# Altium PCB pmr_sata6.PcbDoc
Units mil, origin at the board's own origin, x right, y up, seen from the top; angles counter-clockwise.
Board outline 6299.21 x 3934 mil, 2 copper layers (Top Layer, Bottom Layer); 11 components, 38 nets, 173 pads, 16 vias.
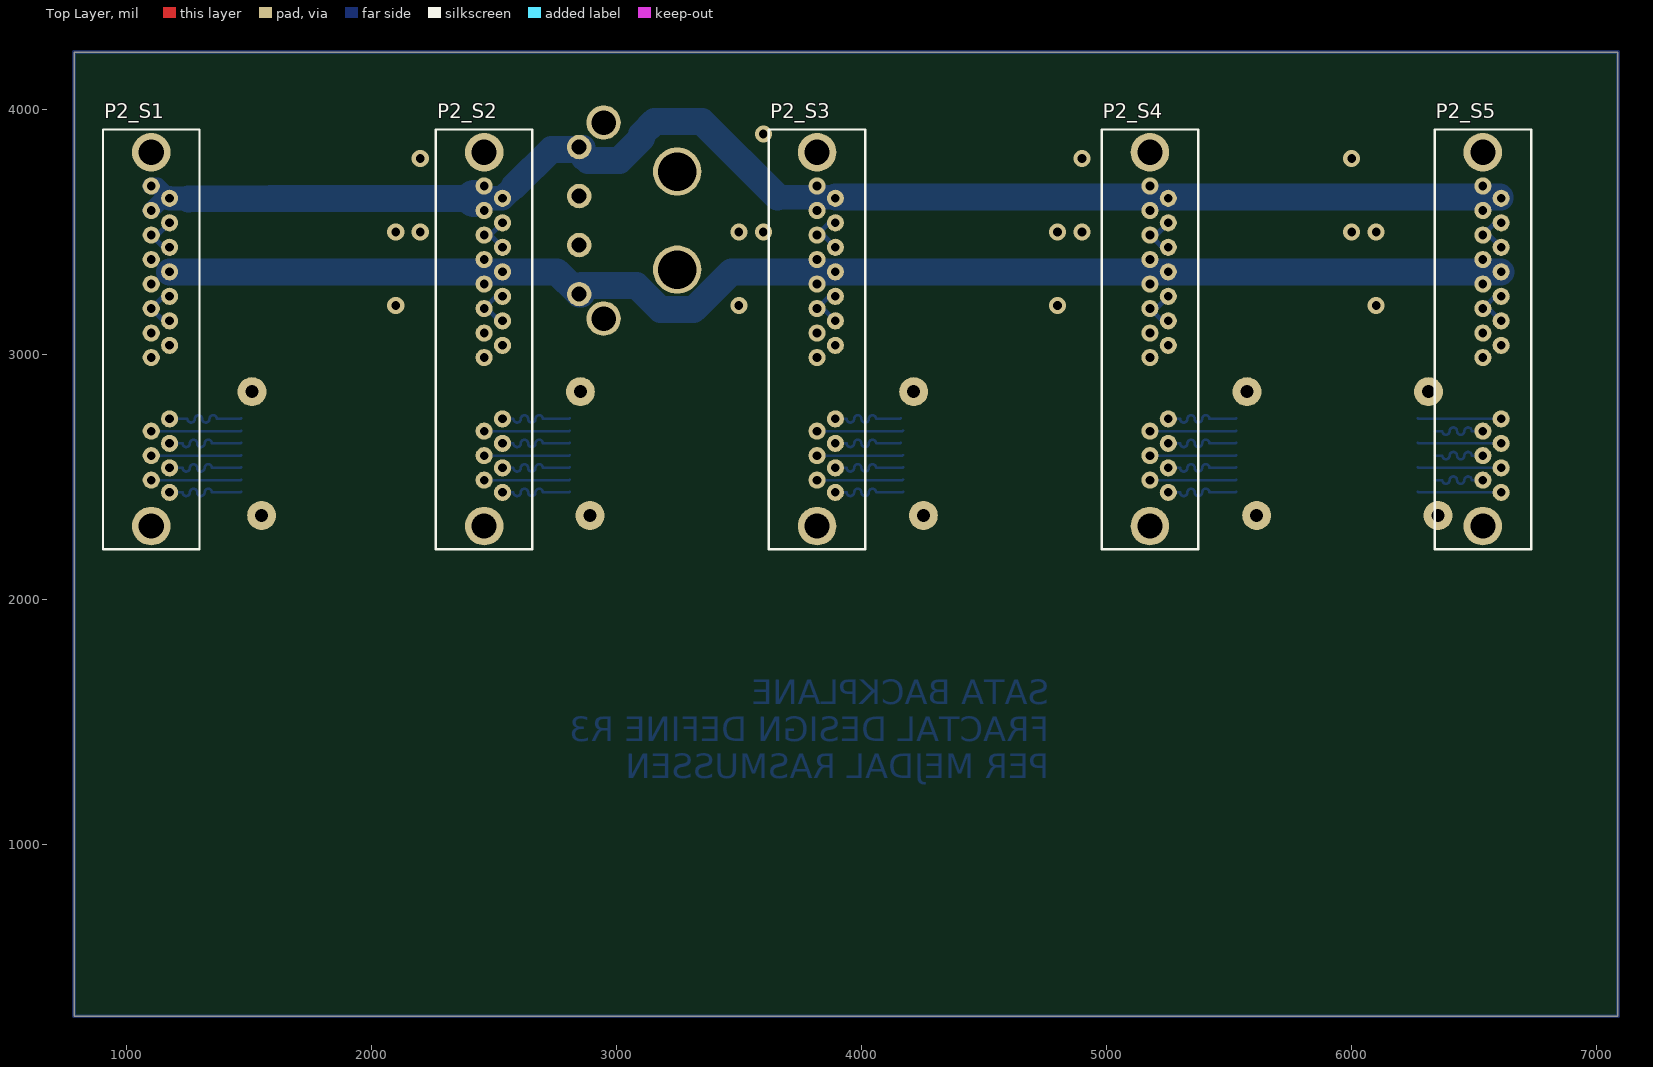
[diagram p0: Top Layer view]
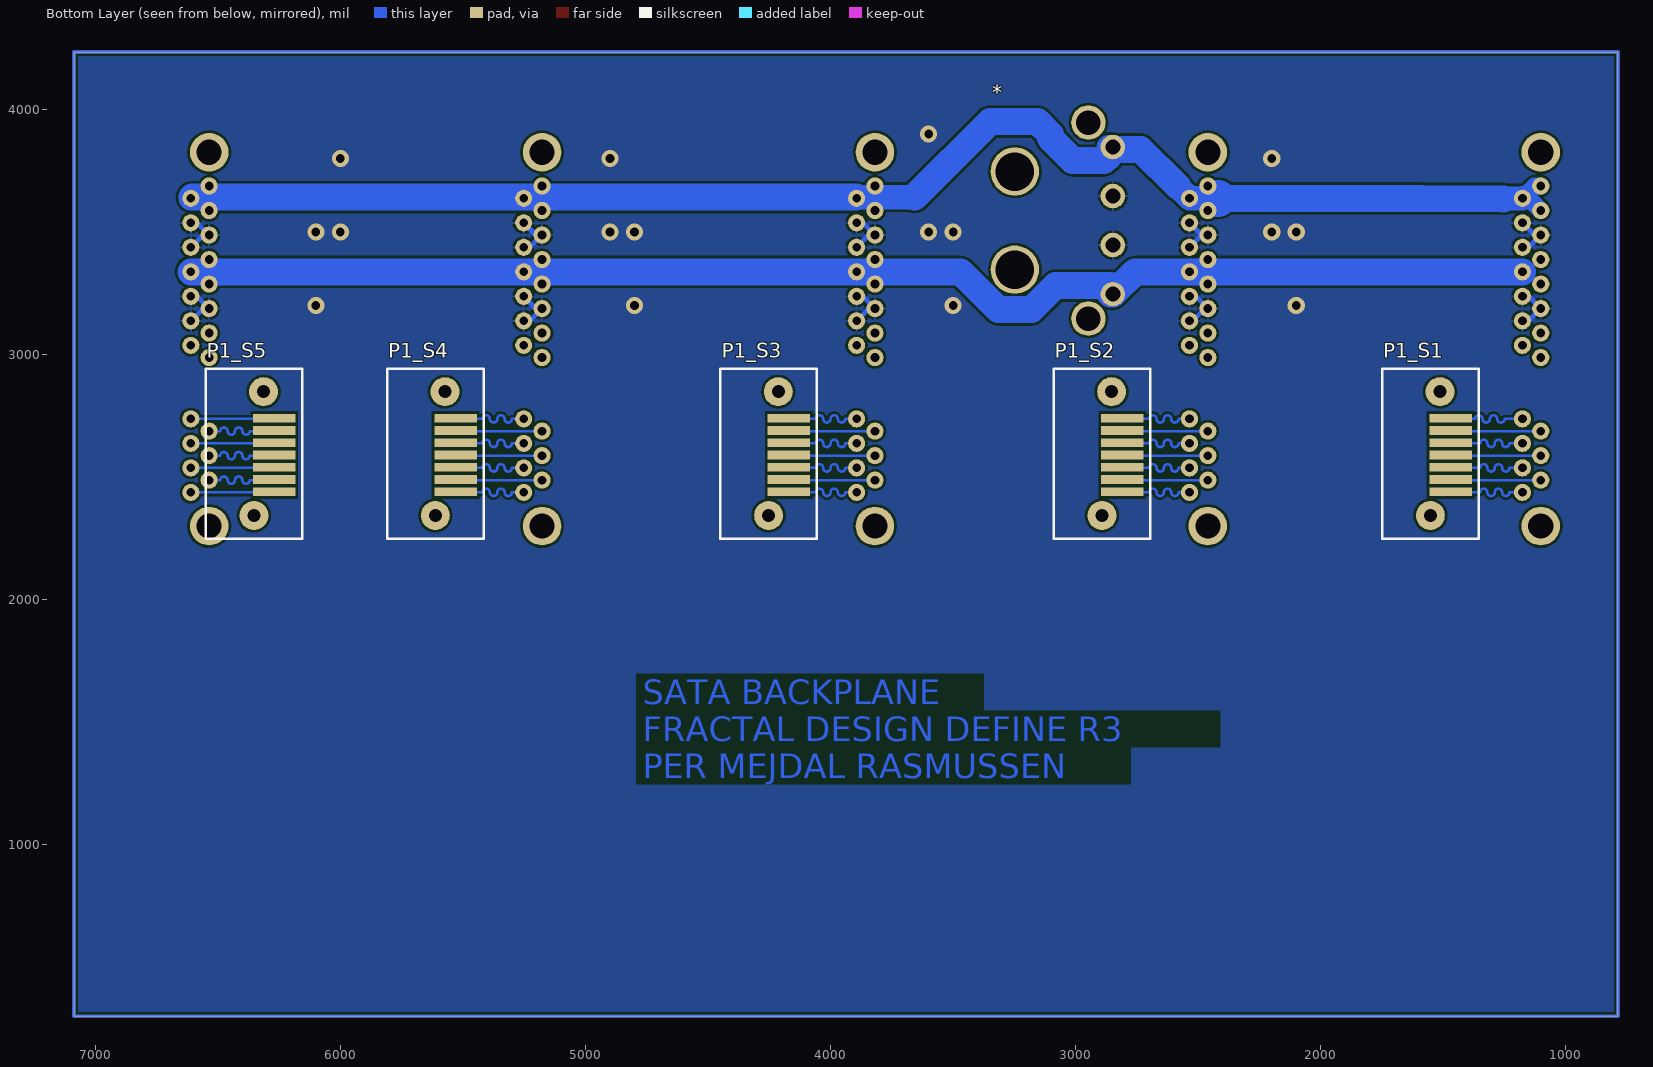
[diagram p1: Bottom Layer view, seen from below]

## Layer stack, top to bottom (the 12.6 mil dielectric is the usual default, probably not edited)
Top Solder: solder mask 0.4, Solder Resist, Dk 3.5
Top Layer: signal copper 1.4
Dielectric1: dielectric 12.6, FR-4, Dk 4.8
Bottom Layer: signal copper 1.4
Bottom Solder: solder mask 0.4, Solder Resist, Dk 3.5

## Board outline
787.4,300 787.4,4234 7086.61,4234 7086.61,300

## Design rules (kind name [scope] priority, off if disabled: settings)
Clearance [All] p1: gap=10
DiffPairsRouting [All] p1: maxlimit=10 minlimit=10 mostfreqgap=10 toplayer_minwidth=10 toplayer_maxwidth=15 toplayer_prefwidth=15 bottomlayer_minwidth=10 bottomlayer_maxwidth=15 bottomlayer_prefwidth=15 maxuncoupledlength=500
PolygonConnect [All] p1: connectstyle=Relief reliefconductorwidth=10 reliefentries=4 polygonreliefangle="90 Angle" airgapwidth=10
RoomDefinition top_level_sheet [InComponentClass('top_level_sheet')] p1 off: confinementstyle=ConfineIn formatcopy=TRUE lockcomponents=FALSE outline 7086.61,393.7 7775.59,393.7 7775.59,1476.38 7086.61,1476.38
RoomDefinition S5 [InComponentClass('S5')] p2 off: confinementstyle=ConfineIn formatcopy=TRUE lockcomponents=FALSE outline 1141.73,4803.15 2086.61,4803.15 2086.61,6692.91 1141.73,6692.91
RoomDefinition S3 [InComponentClass('S3')] p3 off: confinementstyle=ConfineIn formatcopy=TRUE lockcomponents=FALSE outline 2992.13,4520.87 3937.01,4520.87 3937.01,6410.63 2992.13,6410.63
RoomDefinition S2 [InComponentClass('S2')] p4 off: confinementstyle=ConfineIn formatcopy=TRUE lockcomponents=FALSE outline 4251.97,4527.56 5196.85,4527.56 5196.85,6417.32 4251.97,6417.32
RoomDefinition S1 [InComponentClass('S1')] p5 off: confinementstyle=ConfineIn formatcopy=TRUE lockcomponents=FALSE outline 5000,4566.93 5944.88,4566.93 5944.88,6456.69 5000,6456.69
RoomDefinition S4 [InComponentClass('S4')] p6 off: confinementstyle=ConfineIn formatcopy=TRUE lockcomponents=FALSE outline 7570,1160 7280,1160 7280,1590 7570,1590
RoutingVias [All] p1: holewidth=28 width=50 viastyle="Through Hole" minholewidth=28 minwidth=50 maxholewidth=28 maxwidth=50
SilkToSolderMaskClearance SilkscreenOverComponentPads [IsPad] p1: minsilkscreentomaskgap=10 clearancetoexposedcopper=TRUE
SolderMaskExpansion [All] p1: expansion=4
Width [All] p1: maxlimit=500 minlimit=10 preferedwidth=10
28 further rules are at their usual default settings.

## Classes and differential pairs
component class top_level_sheet: *
channel class pmr_sata_single: S1 S2 S3 S4 S5
component class S5: P1_S5 P2_S5
component class S4: P1_S4 P2_S4
component class S3: P1_S3 P2_S3
component class S2: P1_S2 P2_S2
component class S1: P1_S1 P2_S1
differential pair PAIR2_S5: +PAIR2_S5_P -PAIR2_S5_N
differential pair PAIR2_S4: +PAIR2_S4_P -PAIR2_S4_N
differential pair PAIR2_S3: +PAIR2_S3_P -PAIR2_S3_N
differential pair PAIR2_S2: +PAIR2_S2_P -PAIR2_S2_N
differential pair PAIR2_S1: +PAIR2_S1_P -PAIR2_S1_N
differential pair PAIR1_S5: +PAIR1_S5_P -PAIR1_S5_N
differential pair PAIR1_S4: +PAIR1_S4_P -PAIR1_S4_N
differential pair PAIR1_S3: +PAIR1_S3_P -PAIR1_S3_N
differential pair PAIR1_S2: +PAIR1_S2_P -PAIR1_S2_N
differential pair PAIR1_S1: +PAIR1_S1_P -PAIR1_S1_N

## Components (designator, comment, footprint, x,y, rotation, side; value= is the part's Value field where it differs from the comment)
* "PC_PWR_MOLEX" PC_PWR_MOLEX 3248.03,3546.46 r90 bottom
P1_S1 "SATA lille" "PMR_SATA -LILLE NY" 1552.68,2343.15 r270 bottom (schematic designator P1)
P1_S2 "SATA lille" "PMR_SATA -LILLE NY" 2892.68,2343.15 r270 bottom (schematic designator P1)
P1_S3 "SATA lille" "PMR_SATA -LILLE NY" 4252.68,2343.15 r270 bottom (schematic designator P1)
P1_S4 "SATA lille" "PMR_SATA -LILLE NY" 5612.68,2343.15 r270 bottom (schematic designator P1)
P1_S5 "SATA lille" "PMR_SATA -LILLE NY" 6352.68,2343.15 r270 bottom (schematic designator P1)
P2_S1 "SATA STOR" pmr_sata 1102.36,2300 r90 top (schematic designator P2)
P2_S2 "SATA STOR" pmr_sata 2460.63,2300 r90 top (schematic designator P2)
P2_S3 "SATA STOR" pmr_sata 3818.9,2300 r90 top (schematic designator P2)
P2_S4 "SATA STOR" pmr_sata 5177.17,2300 r90 top (schematic designator P2)
P2_S5 "SATA STOR" pmr_sata 6535.43,2300 r90 top (schematic designator P2)

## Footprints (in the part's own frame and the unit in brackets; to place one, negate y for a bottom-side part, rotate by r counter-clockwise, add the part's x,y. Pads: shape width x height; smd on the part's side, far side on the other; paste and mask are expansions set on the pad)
PC_PWR_MOLEX [mil]
  round 100 hole 60: 1(300,-400) 2(100,-400) 3(-100,-400) 4(-300,-400)
  round 140 hole 100: 5(400,-300) 6(-400,-300)
  round 196.85 hole 157.48: 7(-200,0) 8(200,0)
pmr_sata [mm]
  round 1.778 hole 0.9: P1(17.46,0) P2(18.73,-1.9) P3(20,0) P4(21.27,-1.9) P5(22.54,0) P6(23.81,-1.9) P7(25.08,0) P8(26.35,-1.9) P9(27.62,0) P10(28.89,-1.9) P11(30.16,0) P12(31.43,-1.9) P13(32.7,0) P14(33.97,-1.9) P15(35.24,0) S1(3.49,-1.9) S2(4.76,0) S3(6.03,-1.9) S4(7.3,0) S5(8.57,-1.9) S6(9.84,0) S7(11.11,-1.9)
  round 4 hole 2.6: S8(0,0) S8(38.74,0)
  silkscreen extent -2.4,-5 41.1,5
"PMR_SATA -LILLE NY" [mm]
  rect 0.9x4.4 smd: S1(-2.46,2.1) S2(-3.73,2.1) S3(-5,2.1) S4(-6.27,2.1) S5(-7.54,2.1) S6(-8.81,2.1) S7(-10.08,2.1)
  round 3 hole 1.35: S8(-12.83,1) S8(0,0)
  silkscreen extent -15.2,-5 2.4,5

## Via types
v1: diameter 70, hole 35.43, Top Layer to Bottom Layer, 16 vias

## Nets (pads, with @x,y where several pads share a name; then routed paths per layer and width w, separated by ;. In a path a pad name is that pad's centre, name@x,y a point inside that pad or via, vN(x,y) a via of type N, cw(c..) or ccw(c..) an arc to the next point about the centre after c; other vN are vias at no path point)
5V: *.4 P2_S1.P7 P2_S1.P8 P2_S1.P9 P2_S2.P7 P2_S2.P8 P2_S2.P9 P2_S3.P7 P2_S3.P8 P2_S3.P9 P2_S4.P7 P2_S4.P8 P2_S4.P9 P2_S5.P7 P2_S5.P8 P2_S5.P9 | length 5610.5
  Bottom Layer w110: P2_S1.P8 P2_S2.P8 2757.09,3337.4 *.4 2857.11,3246.46 2857.11,3281.46 3081.91,3281.46 3180.34,3183.03 3315.72,3183.03 3470.09,3337.4 P2_S3.P8 P2_S4.P8 P2_S5.P8
12V: *.1 P2_S1.P13 P2_S1.P14 P2_S1.P15 P2_S2.P13 P2_S2.P14 P2_S2.P15 P2_S3.P13 P2_S3.P14 P2_S3.P15 P2_S4.P13 P2_S4.P14 P2_S4.P15 P2_S5.P13 P2_S5.P14 P2_S5.P15 | length 5929.5
  Bottom Layer w70: P2_S1.P13 P2_S1.P14@1152.36,3637.4 ; P2_S1.P15 1127.17,3687.4 P2_S1.P14
  Bottom Layer w100: P2_S1.P14 1255,3635 ; 2420,3637.4 P2_S2.P14 2585,3686.97 ; *.1@2838.43,3836.86 *.1 2864.18,3846.46 *.1@2864.18,3800 ; 3658.27,3641.73 P2_S3.P14@3893.7,3641.73 ; P2_S5.P14@6605.91,3641.73 P2_S5.P14
  Bottom Layer w110: 1255,3635 1590,3636.73 2419.33,3636.73 ; 2585,3686.97 2734.89,3836.86 *.1@2838.43,3836.86 ; 2875.29,3800 2883.83,3791.46 3012.23,3791.46 3103.03,3882.25 3103.03,3898.03 3155,3950 3350,3950 3658.27,3641.73 ; P2_S3.P14@3893.7,3641.73 P2_S5.P14@6605.91,3641.73
  Bottom Layer w150: 2419.33,3636.73 2420,3637.4
GND: *.2 *.3 P2_S1.P4 P2_S1.P5 P2_S1.P6 P2_S1.P10 P2_S1.P11 P2_S1.P12 P2_S2.P4 P2_S2.P5 P2_S2.P6 P2_S2.P10 P2_S2.P11 P2_S2.P12 P2_S3.P4 P2_S3.P5 P2_S3.P6 P2_S3.P10 P2_S3.P11 P2_S3.P12 P2_S4.P4 P2_S4.P5 P2_S4.P6 P2_S4.P10 P2_S4.P11 P2_S4.P12 P2_S5.P4 P2_S5.P5 P2_S5.P6 P2_S5.P10 P2_S5.P11 P2_S5.P12 | length 1935.5
  Bottom Layer w20: P2_S1.P4 1152.36,3137.4 P2_S1.P5 1152.36,3237.4 P2_S1.P6 ; P2_S1.P10 1152.36,3437.4 P2_S1.P11 1127.17,3487.4 P2_S1.P12 ; P2_S2.P11 P2_S2.P11@2485.43,3487.4 ; P2_S2.P4 2522.6,3137.4 2472.6,3187.4 P2_S2.P5 2510.63,3237.4 P2_S2.P6 ; P2_S2.P10@2535.43,3412.4 P2_S2.P10 P2_S2.P11@2485.43,3487.4 ; P2_S2.P12 P2_S2.P11@2485.43,3487.4 ; P2_S3.P4 3843.7,3187.4 P2_S3.P5 3868.9,3237.4 P2_S3.P6 ; P2_S3.P10 3843.7,3487.4 P2_S3.P11 3868.9,3537.4 P2_S3.P12 ; P2_S4.P4 5227.17,3137.4 P2_S4.P5 5201.97,3187.4 P2_S4.P6 P2_S4.P6@5251.97,3262.4 ; P2_S4.P10 5227.17,3437.4 P2_S4.P11 5201.97,3487.4 P2_S4.P12 ; P2_S5.P4 6560.24,3187.4 P2_S5.P5 6585.43,3237.4 P2_S5.P6 ; P2_S5.P10 6560.24,3487.4 P2_S5.P11 6585.43,3537.4 P2_S5.P12
  other v1: 2100,3200 3500,3200 4800,3200 6100,3200 2100,3500 2200,3500 3500,3500 3600,3500 4800,3500 4900,3500 6000,3500 6100,3500 2200,3800 4900,3800 6000,3800 3600,3900
NetP1_S1_S1: P1_S1.S1 P2_S1.S1 | length 339.6
  Bottom Layer w10: P2_S1.S1@1200,2437.4 1230,2437.4 ccw(c1245,2437.4) 1260,2437.4 cw(c1275,2437.4) 1290,2437.4 ccw(c1305,2437.4) 1320,2437.4 cw(c1335,2437.4) 1350,2437.4 1467.4,2437.4 P1_S1.S1
NetP1_S1_S4: P1_S1.S4 P2_S1.S4 | length 368.7
  Bottom Layer w10: P2_S1.S4 1467.4,2587.4 P1_S1.S4
NetP1_S1_S7: P1_S1.S7 P2_S1.S7 | length 362.4
  Bottom Layer w10: P2_S1.S7 1220,2737.4 1250,2737.4 ccw(c1265,2737.4) 1280,2737.4 cw(c1295,2737.4) 1310,2737.4 ccw(c1325,2737.4) 1340,2737.4 cw(c1355,2737.4) 1370,2737.4 1378.68,2737.4 1467.4,2737.4 P1_S1.S7
NetP1_S2_S1: P1_S2.S1 P2_S2.S1 | length 329.6
  Bottom Layer w10: P2_S2.S1@2550,2437.4 2580,2437.4 ccw(c2595,2437.4) 2610,2437.4 cw(c2625,2437.4) 2640,2437.4 ccw(c2655,2437.4) 2670,2437.4 cw(c2685,2437.4) 2700,2437.4 2807.4,2437.4 P1_S2.S1
NetP1_S2_S4: P1_S2.S4 P2_S2.S4 | length 350.4
  Bottom Layer w10: P2_S2.S4 2807.4,2587.4 P1_S2.S4
NetP1_S2_S7: P1_S2.S7 P2_S2.S7 | length 329.6
  Bottom Layer w10: P2_S2.S7@2550,2737.4 2580,2737.4 ccw(c2595,2737.4) 2610,2737.4 cw(c2625,2737.4) 2640,2737.4 ccw(c2655,2737.4) 2670,2737.4 cw(c2685,2737.4) 2700,2737.4 2807.4,2737.4 P1_S2.S7
NetP1_S3_S1: P1_S3.S1 P2_S3.S1 | length 329.6
  Bottom Layer w10: P2_S3.S1@3910,2437.4 3940,2437.4 ccw(c3955,2437.4) 3970,2437.4 cw(c3985,2437.4) 4000,2437.4 ccw(c4015,2437.4) 4030,2437.4 cw(c4045,2437.4) 4060,2437.4 4167.4,2437.4 P1_S3.S1
NetP1_S3_S4: P1_S3.S4 P2_S3.S4 | length 352.2
  Bottom Layer w10: P2_S3.S4 4167.4,2587.4 P1_S3.S4
NetP1_S3_S7: P1_S3.S7 P2_S3.S7 | length 319.6
  Bottom Layer w10: P2_S3.S7@3910,2737.4 3940,2737.4 ccw(c3955,2737.4) 3970,2737.4 cw(c3985,2737.4) 4000,2737.4 ccw(c4015,2737.4) 4030,2737.4 cw(c4045,2737.4) 4060,2737.4 4157.4,2737.4 P1_S3.S7@4160,2740
NetP1_S4_S1: P1_S4.S1 P2_S4.S1 | length 329.6
  Bottom Layer w10: P2_S4.S1@5270,2437.4 5300,2437.4 ccw(c5315,2437.4) 5330,2437.4 cw(c5345,2437.4) 5360,2437.4 ccw(c5375,2437.4) 5390,2437.4 cw(c5405,2437.4) 5420,2437.4 5527.4,2437.4 P1_S4.S1
NetP1_S4_S4: P1_S4.S4 P2_S4.S4 | length 353.9
  Bottom Layer w10: P2_S4.S4 5527.4,2587.4 P1_S4.S4
NetP1_S4_S7: P1_S4.S7 P2_S4.S7 | length 329.6
  Bottom Layer w10: P2_S4.S7@5270,2737.4 5300,2737.4 ccw(c5315,2737.4) 5330,2737.4 cw(c5345,2737.4) 5360,2737.4 ccw(c5375,2737.4) 5390,2737.4 cw(c5405,2737.4) 5420,2737.4 5527.4,2737.4 P1_S4.S7
NetP1_S5_S1: P1_S5.S1 P2_S5.S1 | length 341.3
  Bottom Layer w10: P1_S5.S1 6272.6,2437.4 P2_S5.S1
NetP1_S5_S4: P1_S5.S4 P2_S5.S4 | length 227.2
  Bottom Layer w10: P1_S5.S4@6340,2587.4 6370,2587.4 ccw(c6385,2587.4) 6400,2587.4 cw(c6415,2587.4) 6430,2587.4 ccw(c6445,2587.4) 6460,2587.4 cw(c6475,2587.4) 6490,2587.4 6498.68,2587.4
NetP1_S5_S7: P1_S5.S7 P2_S5.S7 | length 341.3
  Bottom Layer w10: P1_S5.S7 6272.6,2737.4 P2_S5.S7
PAIR1_S1_N: P1_S1.S2 P2_S1.S2 | length 368.7
  Bottom Layer w10: P2_S1.S2 1467.4,2487.4 P1_S1.S2
PAIR1_S1_P: P1_S1.S3 P2_S1.S3 | length 339.6
  Bottom Layer w10: P2_S1.S3@1200,2537.4 1230,2537.4 ccw(c1245,2537.4) 1260,2537.4 cw(c1275,2537.4) 1290,2537.4 ccw(c1305,2537.4) 1320,2537.4 cw(c1335,2537.4) 1350,2537.4 1467.4,2537.4 P1_S1.S3
PAIR1_S2_N: P1_S2.S2 P2_S2.S2 | length 350.4
  Bottom Layer w10: P2_S2.S2 2807.4,2487.4 P1_S2.S2
PAIR1_S2_P: P1_S2.S3 P2_S2.S3 | length 329.6
  Bottom Layer w10: P2_S2.S3@2550,2537.4 2580,2537.4 ccw(c2595,2537.4) 2610,2537.4 cw(c2625,2537.4) 2640,2537.4 ccw(c2655,2537.4) 2670,2537.4 cw(c2685,2537.4) 2700,2537.4 2807.4,2537.4 P1_S2.S3
PAIR1_S3_N: P1_S3.S2 P2_S3.S2 | length 352.2
  Bottom Layer w10: P2_S3.S2 4167.4,2487.4 P1_S3.S2
PAIR1_S3_P: P1_S3.S3 P2_S3.S3 | length 329.6
  Bottom Layer w10: P2_S3.S3@3910,2537.4 3940,2537.4 ccw(c3955,2537.4) 3970,2537.4 cw(c3985,2537.4) 4000,2537.4 ccw(c4015,2537.4) 4030,2537.4 cw(c4045,2537.4) 4060,2537.4 4167.4,2537.4 P1_S3.S3
PAIR1_S4_N: P1_S4.S2 P2_S4.S2 | length 367.7
  Bottom Layer w10: P2_S4.S2 5177.17,2497.17 5186.93,2487.4 5527.4,2487.4 P1_S4.S2
PAIR1_S4_P: P1_S4.S3 P2_S4.S3 | length 329.6
  Bottom Layer w10: P2_S4.S3@5270,2537.4 5300,2537.4 ccw(c5315,2537.4) 5330,2537.4 cw(c5345,2537.4) 5360,2537.4 ccw(c5375,2537.4) 5390,2537.4 cw(c5405,2537.4) 5420,2537.4 5527.4,2537.4 P1_S4.S3
PAIR1_S5_N: P1_S5.S2 P2_S5.S2 | length 227.2
  Bottom Layer w10: P1_S5.S2@6340,2487.4 6370,2487.4 ccw(c6385,2487.4) 6400,2487.4 cw(c6415,2487.4) 6430,2487.4 ccw(c6445,2487.4) 6460,2487.4 cw(c6475,2487.4) 6490,2487.4 6498.68,2487.4
PAIR1_S5_P: P1_S5.S3 P2_S5.S3 | length 341.3
  Bottom Layer w10: P1_S5.S3 6272.6,2537.4 P2_S5.S3
PAIR2_S1_N: P1_S1.S5 P2_S1.S5 | length 362.4
  Bottom Layer w10: P2_S1.S5 1230,2637.4 ccw(c1245,2637.4) 1260,2637.4 cw(c1275,2637.4) 1290,2637.4 ccw(c1305,2637.4) 1320,2637.4 cw(c1335,2637.4) 1350,2637.4 1467.4,2637.4 P1_S1.S5
PAIR2_S1_P: P1_S1.S6 P2_S1.S6 | length 368.7
  Bottom Layer w10: P2_S1.S6 1467.4,2687.4 P1_S1.S6
PAIR2_S2_N: P1_S2.S5 P2_S2.S5 | length 329.6
  Bottom Layer w10: P2_S2.S5@2550,2637.4 2580,2637.4 ccw(c2595,2637.4) 2610,2637.4 cw(c2625,2637.4) 2640,2637.4 ccw(c2655,2637.4) 2670,2637.4 cw(c2685,2637.4) 2700,2637.4 2807.4,2637.4 P1_S2.S5
PAIR2_S2_P: P1_S2.S6 P2_S2.S6 | length 350.4
  Bottom Layer w10: P2_S2.S6 2807.4,2687.4 P1_S2.S6
PAIR2_S3_N: P1_S3.S5 P2_S3.S5 | length 319.6
  Bottom Layer w10: P2_S3.S5@3910,2637.4 3940,2637.4 ccw(c3955,2637.4) 3970,2637.4 cw(c3985,2637.4) 4000,2637.4 ccw(c4015,2637.4) 4030,2637.4 cw(c4045,2637.4) 4060,2637.4 4157.4,2637.4 P1_S3.S5@4160,2640
PAIR2_S3_P: P1_S3.S6 P2_S3.S6 | length 352.2
  Bottom Layer w10: P2_S3.S6 4167.4,2687.4 P1_S3.S6
PAIR2_S4_N: P1_S4.S5 P2_S4.S5 | length 329.6
  Bottom Layer w10: P2_S4.S5@5270,2637.4 5300,2637.4 ccw(c5315,2637.4) 5330,2637.4 cw(c5345,2637.4) 5360,2637.4 ccw(c5375,2637.4) 5390,2637.4 cw(c5405,2637.4) 5420,2637.4 5527.4,2637.4 P1_S4.S5
PAIR2_S4_P: P1_S4.S6 P2_S4.S6 | length 353.9
  Bottom Layer w10: P2_S4.S6 5527.4,2687.4 P1_S4.S6
PAIR2_S5_N: P1_S5.S5 P2_S5.S5 | length 341.3
  Bottom Layer w10: P1_S5.S5 6272.6,2637.4 P2_S5.S5
PAIR2_S5_P: P1_S5.S6 P2_S5.S6 | length 227.2
  Bottom Layer w10: P1_S5.S6@6340,2687.4 6370,2687.4 ccw(c6385,2687.4) 6400,2687.4 cw(c6415,2687.4) 6430,2687.4 ccw(c6445,2687.4) 6460,2687.4 cw(c6475,2687.4) 6490,2687.4 6498.68,2687.4
pads on no net: *.5 *.6 *.7 *.8 P1_S1.S8 P1_S2.S8 P1_S3.S8 P1_S4.S8 P1_S5.S8 P2_S1.P1 P2_S1.P2 P2_S1.P3 P2_S1.S8 P2_S2.P1 P2_S2.P2 P2_S2.P3 P2_S2.S8 P2_S3.P1 P2_S3.P2 P2_S3.P3 P2_S3.S8 P2_S4.P1 P2_S4.P2 P2_S4.P3 P2_S4.S8 P2_S5.P1 P2_S5.P2 P2_S5.P3 P2_S5.S8
copper on no net: | length 20466.4
  Bottom Layer w15: 787.4,300 7086.61,300 7086.61,4234 787.4,4234 787.4,300

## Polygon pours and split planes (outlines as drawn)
GND on Bottom Layer "BOT GND" (solid, pour order 0): 787.4,300 787.4,4234 7086.61,4234 7086.61,300

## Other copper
Bottom Layer:
  text "SATA BACKPLANE" at 4767,1573 h100
  text "FRACTAL DESIGN DEFINE R3" at 4767,1422 h100
  text "PER MEJDAL RASMUSSEN" at 4767,1271 h100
